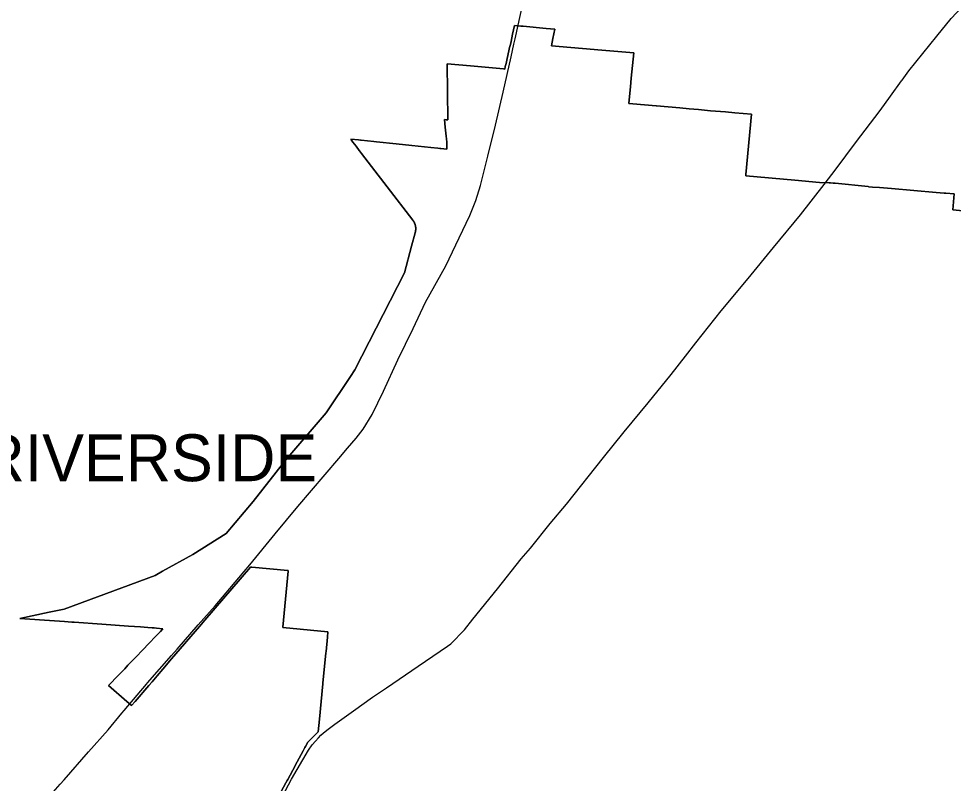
# Model space of a CAD drawing. Extents: x 0 to 34, y 0 to 22.
# Drawn here: x 5.4241 to 5.5845, y 15.3647 to 15.4958 of the extents above; entities that cross this region are included whole.
import ezdxf

# ---------------------------------------------------------------- set-up
doc = ezdxf.new("R2010")
doc.units = 0
for name, color, linetype in [('GM_X_Corporation', 7, 'Continuous'), ('GM_X_Corporation_Text', 7, 'Continuous'), ('GM_X_State_Route', 7, 'Continuous')]:
    doc.layers.add(name, color=color, linetype=linetype)

msp = doc.modelspace()

# ---------------------------------------------------------------- linework, layer by layer
at = {"layer": 'GM_X_Corporation'}
for points in [[(5.46726, 15.35978), (5.46998, 15.36478), (5.47019, 15.36518), (5.4703, 15.36537), (5.47154, 15.36769), (5.47159, 15.36777), (5.47291, 15.37024), (5.47293, 15.37027), (5.47306, 15.37051), (5.47311, 15.37061), (5.47317, 15.37071), (5.4732, 15.37078), (5.47322, 15.37081), (5.47333, 15.37102), (5.47371, 15.37172), (5.47554, 15.37351), (5.47575, 15.37568), (5.47633, 15.38176), (5.47634, 15.38184), (5.47684, 15.38706), (5.47687, 15.38731), (5.4771, 15.38975), (5.47719, 15.3907), (5.47718, 15.3907), (5.46942, 15.39144), (5.46942, 15.39149), (5.47034, 15.4011), (5.47035, 15.40118), (5.47031, 15.40118), (5.46413, 15.40177), (5.46389, 15.40179), (5.45607, 15.39269), (5.45514, 15.39161), (5.45034, 15.38602), (5.44886, 15.38429), (5.44787, 15.38313), (5.44702, 15.38212), (5.44646, 15.38148), (5.44408, 15.37871), (5.4435, 15.37802), (5.4431, 15.37836), (5.44303, 15.37842), (5.4427, 15.37871), (5.43952, 15.38145), (5.44008, 15.38203), (5.44017, 15.38212), (5.44064, 15.38261), (5.44098, 15.38297), (5.44175, 15.38377), (5.44231, 15.38435), (5.44287, 15.38494), (5.44343, 15.38552), (5.44398, 15.3861), (5.44454, 15.38668), (5.4451, 15.38726), (5.44566, 15.38784), (5.44622, 15.38842), (5.44663, 15.38886), (5.44677, 15.389), (5.44733, 15.38958), (5.44788, 15.39015), (5.44816, 15.39045), (5.44821, 15.3905), (5.44843, 15.39074), (5.44887, 15.39121), (5.44776, 15.3913), (5.44735, 15.39134), (5.44704, 15.39137), (5.4463, 15.39142), (5.44503, 15.39151), (5.44296, 15.39166), (5.43841, 15.39198), (5.43365, 15.39232), (5.43322, 15.39235), (5.43196, 15.39244), (5.43024, 15.39256), (5.4243, 15.39298), (5.42937, 15.39403), (5.4319, 15.39456), (5.44754, 15.40034), (5.4488, 15.40105), (5.454, 15.40396), (5.45975, 15.40755), (5.46434, 15.41304), (5.46996, 15.42018), (5.47687, 15.42823), (5.48108, 15.43448), (5.48182, 15.43559), (5.49033, 15.45223), (5.4915, 15.45682), (5.49216, 15.45913), (5.49218, 15.45918), (5.49218, 15.45918), (5.49218, 15.4592), (5.49218, 15.45921), (5.49219, 15.45922), (5.49219, 15.45922), (5.49219, 15.45924), (5.49219, 15.45925), (5.4922, 15.45926), (5.4922, 15.45926), (5.4922, 15.45928), (5.4922, 15.45929), (5.49221, 15.4593), (5.49221, 15.45931), (5.49221, 15.45932), (5.49221, 15.45933), (5.49221, 15.45934), (5.49222, 15.45935), (5.49222, 15.45936), (5.49222, 15.45937), (5.49222, 15.45938), (5.49222, 15.45939), (5.49223, 15.4594), (5.49223, 15.45941), (5.49223, 15.45942), (5.49223, 15.45943), (5.49223, 15.45944), (5.49223, 15.45946), (5.49224, 15.45946), (5.49224, 15.45947), (5.49224, 15.45948), (5.49224, 15.4595), (5.49224, 15.45951), (5.49224, 15.45951), (5.49224, 15.45953), (5.49224, 15.45954), (5.49225, 15.45955), (5.49225, 15.45956), (5.49225, 15.45957), (5.49225, 15.45958), (5.49225, 15.45959), (5.49225, 15.4596), (5.49225, 15.45961), (5.49225, 15.45962), (5.49225, 15.45963), (5.49225, 15.45964), (5.49225, 15.45965), (5.49226, 15.45967), (5.49226, 15.45967), (5.49226, 15.45968), (5.49226, 15.45969), (5.49226, 15.45971), (5.49226, 15.45972), (5.49226, 15.45972), (5.49226, 15.45974), (5.49226, 15.45975), (5.49226, 15.45976), (5.49226, 15.45977), (5.49226, 15.45978), (5.49226, 15.45979), (5.49226, 15.4598), (5.49226, 15.45981), (5.49226, 15.45982), (5.49226, 15.45983), (5.49226, 15.45984), (5.49226, 15.45985), (5.49226, 15.45986), (5.49226, 15.45988), (5.49226, 15.45988), (5.49226, 15.45989), (5.49226, 15.4599), (5.49226, 15.45992), (5.49226, 15.45993), (5.49226, 15.45993), (5.49226, 15.45995), (5.49225, 15.45996), (5.49225, 15.45997), (5.49225, 15.45998), (5.49225, 15.45999), (5.49225, 15.46), (5.49225, 15.46001), (5.49225, 15.46002), (5.49225, 15.46003), (5.49225, 15.46004), (5.49225, 15.46005), (5.49225, 15.46006), (5.49225, 15.46007), (5.49224, 15.46009), (5.49224, 15.46009), (5.49224, 15.4601), (5.49224, 15.46011), (5.49224, 15.46013), (5.49224, 15.46014), (5.49224, 15.46014), (5.49223, 15.46016), (5.49223, 15.46017), (5.49223, 15.46018), (5.49223, 15.46018), (5.49223, 15.4602), (5.49223, 15.46021), (5.49222, 15.46022), (5.49222, 15.46023), (5.49222, 15.46024), (5.49222, 15.46025), (5.49222, 15.46026), (5.49222, 15.46027), (5.49221, 15.46028), (5.49221, 15.46029), (5.49221, 15.4603), (5.49221, 15.46031), (5.4922, 15.46032), (5.4922, 15.46033), (5.4922, 15.46034), (5.4922, 15.46035), (5.4922, 15.46036), (5.49219, 15.46038), (5.49219, 15.46038), (5.49219, 15.46039), (5.49218, 15.4604), (5.49218, 15.46042), (5.49218, 15.46042), (5.49218, 15.46043), (5.49217, 15.46044), (5.49217, 15.46046), (5.49217, 15.46046), (5.49217, 15.46047), (5.49216, 15.46048), (5.49216, 15.4605), (5.49216, 15.4605), (5.49215, 15.46051), (5.49215, 15.46052), (5.49215, 15.46054), (5.49214, 15.46054), (5.49214, 15.46055), (5.49214, 15.46056), (5.49213, 15.46058), (5.49213, 15.46058), (5.49213, 15.46059), (5.49212, 15.4606), (5.49212, 15.46062), (5.49212, 15.46062), (5.49211, 15.46063), (5.49211, 15.46064), (5.49211, 15.46066), (5.4921, 15.46066), (5.4921, 15.46067), (5.49209, 15.46068), (5.49209, 15.4607), (5.49209, 15.4607), (5.49208, 15.46071), (5.49208, 15.46072), (5.49207, 15.46073), (5.49207, 15.46074), (5.49207, 15.46075), (5.49206, 15.46076), (5.49206, 15.46077), (5.49205, 15.46078), (5.49205, 15.46079), (5.49205, 15.4608), (5.49204, 15.46081), (5.49204, 15.46082), (5.49203, 15.46083), (5.49203, 15.46084), (5.49202, 15.46085), (5.49202, 15.46086), (5.49202, 15.46086), (5.49201, 15.46088), (5.492, 15.46089), (5.492, 15.46089), (5.492, 15.4609), (5.49199, 15.46091), (5.49199, 15.46091), (5.49198, 15.46093), (5.49198, 15.46093), (5.49198, 15.46094), (5.49197, 15.46095), (5.49197, 15.46096), (5.49196, 15.46097), (5.49196, 15.46098), (5.49195, 15.46099), (5.49194, 15.461), (5.49194, 15.46101), (5.49194, 15.46101), (5.49193, 15.46102), (5.49192, 15.46104), (5.49192, 15.46104), (5.49192, 15.46105), (5.49191, 15.46106), (5.49191, 15.46106), (5.4919, 15.46107), (5.4919, 15.46108), (5.49189, 15.46108), (5.49189, 15.4611), (5.49188, 15.46111), (5.49188, 15.46111), (5.49187, 15.46112), (5.49186, 15.46113), (5.49186, 15.46113), (5.49186, 15.46114), (5.49185, 15.46115), (5.49185, 15.46116), (5.49184, 15.46117), (5.49184, 15.46117), (5.49183, 15.46118), (5.49183, 15.46118), (5.49182, 15.46119), (5.49182, 15.4612), (5.49182, 15.4612), (5.49181, 15.46121), (5.4918, 15.46122), (5.4918, 15.46122), (5.49179, 15.46124), (5.49178, 15.46125), (5.49178, 15.46125), (5.49177, 15.46126), (5.49175, 15.46129), (5.48734, 15.46698), (5.48467, 15.47048), (5.48296, 15.47271), (5.4826, 15.47319), (5.48255, 15.47325), (5.48202, 15.47395), (5.48148, 15.47467), (5.4811, 15.47518), (5.48112, 15.47517), (5.48241, 15.47504), (5.48279, 15.475), (5.4829, 15.47499), (5.48509, 15.47476), (5.48553, 15.47472), (5.48889, 15.47437), (5.4916, 15.47409), (5.49485, 15.47376), (5.49606, 15.47363), (5.49639, 15.4736), (5.49655, 15.47358), (5.4976, 15.47348), (5.4976, 15.47469), (5.49738, 15.47674), (5.49733, 15.47726), (5.4972, 15.47852), (5.4975, 15.47849), (5.49778, 15.47847), (5.49778, 15.4785), (5.49762, 15.48811), (5.50163, 15.48775), (5.50733, 15.48722), (5.50752, 15.4872), (5.50763, 15.48765), (5.50775, 15.48818), (5.50787, 15.48872), (5.5083, 15.49059), (5.50843, 15.49114), (5.50844, 15.49117), (5.50861, 15.49191), (5.50888, 15.49316), (5.50921, 15.49467), (5.5097, 15.49462), (5.50974, 15.49462), (5.51028, 15.49457), (5.51071, 15.49453), (5.51466, 15.49417), (5.51615, 15.49403), (5.5158, 15.49246), (5.51553, 15.49121), (5.52421, 15.49045), (5.52967, 15.48998), (5.52925, 15.48566), (5.52911, 15.48414), (5.52884, 15.48135), (5.52883, 15.4813), (5.52949, 15.48124), (5.53152, 15.48106), (5.53152, 15.48106), (5.53353, 15.48089), (5.53355, 15.48088), (5.53756, 15.48053), (5.53757, 15.48053), (5.53916, 15.48039), (5.53917, 15.48039), (5.54076, 15.48025), (5.54078, 15.48025), (5.54284, 15.48006), (5.54286, 15.48006), (5.5454, 15.47984), (5.54543, 15.47984), (5.547, 15.4797), (5.54703, 15.47969), (5.54989, 15.47944), (5.54891, 15.46909), (5.54889, 15.46888), (5.55733, 15.46813), (5.56153, 15.46776), (5.5626, 15.46767), (5.56266, 15.46775), (5.56321, 15.4677), (5.56344, 15.46768), (5.56386, 15.46764), (5.56387, 15.46763), (5.56422, 15.4676), (5.56989, 15.46704), (5.57002, 15.46702), (5.57065, 15.46696), (5.57183, 15.46686), (5.57387, 15.46669), (5.58157, 15.46605), (5.58295, 15.46594), (5.58313, 15.46593), (5.58321, 15.46592), (5.58465, 15.46578), (5.58442, 15.46303), (5.59342, 15.46213)], [(5.59342, 15.46213), (5.58442, 15.46303), (5.58465, 15.46578), (5.58321, 15.46592), (5.58313, 15.46593), (5.58295, 15.46594), (5.58157, 15.46605), (5.57387, 15.46669), (5.57183, 15.46686), (5.57065, 15.46696), (5.57002, 15.46702), (5.56989, 15.46704), (5.56422, 15.4676), (5.56387, 15.46763), (5.56386, 15.46764), (5.56344, 15.46768), (5.56321, 15.4677), (5.56266, 15.46775), (5.5626, 15.46767), (5.56153, 15.46776), (5.55733, 15.46813), (5.54889, 15.46888), (5.54891, 15.46909), (5.54989, 15.47944), (5.54703, 15.47969), (5.547, 15.4797), (5.54543, 15.47984), (5.5454, 15.47984), (5.54286, 15.48006), (5.54284, 15.48006), (5.54078, 15.48025), (5.54076, 15.48025), (5.53917, 15.48039), (5.53916, 15.48039), (5.53757, 15.48053), (5.53756, 15.48053), (5.53355, 15.48088), (5.53353, 15.48089), (5.53152, 15.48106), (5.53152, 15.48106), (5.52949, 15.48124), (5.52883, 15.4813), (5.52884, 15.48135), (5.52911, 15.48414), (5.52925, 15.48566), (5.52967, 15.48998), (5.52421, 15.49045), (5.51553, 15.49121), (5.5158, 15.49246), (5.51615, 15.49403), (5.51466, 15.49417), (5.51071, 15.49453), (5.51028, 15.49457), (5.50974, 15.49462), (5.5097, 15.49462), (5.50921, 15.49467), (5.50888, 15.49316), (5.50861, 15.49191), (5.50844, 15.49117), (5.50843, 15.49114), (5.5083, 15.49059), (5.50787, 15.48872), (5.50775, 15.48818), (5.50763, 15.48765), (5.50752, 15.4872), (5.50733, 15.48722), (5.50163, 15.48775), (5.49762, 15.48811), (5.49778, 15.4785), (5.49778, 15.47847), (5.4975, 15.47849), (5.4972, 15.47852), (5.49733, 15.47726), (5.49738, 15.47674), (5.4976, 15.47468), (5.4976, 15.47348), (5.49655, 15.47358), (5.49639, 15.4736), (5.49606, 15.47363), (5.49485, 15.47376), (5.4916, 15.47409), (5.48889, 15.47437), (5.48553, 15.47472), (5.48509, 15.47476), (5.4829, 15.47499), (5.48279, 15.475), (5.48241, 15.47504), (5.48112, 15.47517), (5.4811, 15.47518), (5.48148, 15.47467), (5.48202, 15.47395), (5.48255, 15.47325), (5.4826, 15.47319), (5.48296, 15.47271), (5.48467, 15.47048), (5.48734, 15.46698), (5.49175, 15.46129), (5.49177, 15.46126), (5.49178, 15.46125), (5.49178, 15.46125), (5.49179, 15.46124), (5.4918, 15.46122), (5.4918, 15.46122), (5.49181, 15.46121), (5.49182, 15.4612), (5.49182, 15.4612), (5.49182, 15.46119), (5.49183, 15.46118), (5.49183, 15.46118), (5.49184, 15.46117), (5.49184, 15.46117), (5.49185, 15.46116), (5.49185, 15.46115), (5.49186, 15.46114), (5.49186, 15.46113), (5.49186, 15.46113), (5.49187, 15.46112), (5.49188, 15.46111), (5.49188, 15.46111), (5.49189, 15.4611), (5.49189, 15.46108), (5.4919, 15.46108), (5.4919, 15.46107), (5.49191, 15.46106), (5.49191, 15.46106), (5.49192, 15.46105), (5.49192, 15.46104), (5.49192, 15.46104), (5.49193, 15.46102), (5.49194, 15.46101), (5.49194, 15.46101), (5.49194, 15.461), (5.49195, 15.46099), (5.49196, 15.46098), (5.49196, 15.46097), (5.49197, 15.46096), (5.49197, 15.46095), (5.49198, 15.46094), (5.49198, 15.46093), (5.49198, 15.46093), (5.49199, 15.46091), (5.49199, 15.46091), (5.492, 15.4609), (5.492, 15.46089), (5.492, 15.46089), (5.49201, 15.46088), (5.49202, 15.46086), (5.49202, 15.46086), (5.49202, 15.46085), (5.49203, 15.46084), (5.49203, 15.46083), (5.49204, 15.46082), (5.49204, 15.46081), (5.49205, 15.4608), (5.49205, 15.46079), (5.49205, 15.46078), (5.49206, 15.46077), (5.49206, 15.46076), (5.49207, 15.46075), (5.49207, 15.46074), (5.49207, 15.46073), (5.49208, 15.46072), (5.49208, 15.46071), (5.49209, 15.4607), (5.49209, 15.4607), (5.49209, 15.46068), (5.4921, 15.46067), (5.4921, 15.46066), (5.49211, 15.46066), (5.49211, 15.46064), (5.49211, 15.46063), (5.49212, 15.46062), (5.49212, 15.46062), (5.49212, 15.4606), (5.49213, 15.46059), (5.49213, 15.46058), (5.49213, 15.46058), (5.49214, 15.46056), (5.49214, 15.46055), (5.49214, 15.46054), (5.49215, 15.46054), (5.49215, 15.46052), (5.49215, 15.46051), (5.49216, 15.4605), (5.49216, 15.4605), (5.49216, 15.46048), (5.49217, 15.46047), (5.49217, 15.46046), (5.49217, 15.46046), (5.49217, 15.46044), (5.49218, 15.46043), (5.49218, 15.46042), (5.49218, 15.46042), (5.49218, 15.4604), (5.49219, 15.46039), (5.49219, 15.46038), (5.49219, 15.46038), (5.4922, 15.46036), (5.4922, 15.46035), (5.4922, 15.46034), (5.4922, 15.46033), (5.4922, 15.46032), (5.49221, 15.46031), (5.49221, 15.4603), (5.49221, 15.46029), (5.49221, 15.46028), (5.49222, 15.46027), (5.49222, 15.46026), (5.49222, 15.46025), (5.49222, 15.46024), (5.49222, 15.46023), (5.49222, 15.46022), (5.49223, 15.46021), (5.49223, 15.4602), (5.49223, 15.46018), (5.49223, 15.46018), (5.49223, 15.46017), (5.49223, 15.46016), (5.49224, 15.46014), (5.49224, 15.46014), (5.49224, 15.46013), (5.49224, 15.46011), (5.49224, 15.4601), (5.49224, 15.46009), (5.49224, 15.46009), (5.49225, 15.46007), (5.49225, 15.46006), (5.49225, 15.46005), (5.49225, 15.46004), (5.49225, 15.46003), (5.49225, 15.46002), (5.49225, 15.46001), (5.49225, 15.46), (5.49225, 15.45999), (5.49225, 15.45998), (5.49225, 15.45997), (5.49225, 15.45996), (5.49226, 15.45995), (5.49226, 15.45993), (5.49226, 15.45993), (5.49226, 15.45992), (5.49226, 15.4599), (5.49226, 15.45989), (5.49226, 15.45988), (5.49226, 15.45988), (5.49226, 15.45986), (5.49226, 15.45985), (5.49226, 15.45984), (5.49226, 15.45983), (5.49226, 15.45982), (5.49226, 15.45981), (5.49226, 15.4598), (5.49226, 15.45979), (5.49226, 15.45978), (5.49226, 15.45977), (5.49226, 15.45976), (5.49226, 15.45975), (5.49226, 15.45974), (5.49226, 15.45972), (5.49226, 15.45972), (5.49226, 15.45971), (5.49226, 15.45969), (5.49226, 15.45968), (5.49226, 15.45967), (5.49226, 15.45967), (5.49225, 15.45965), (5.49225, 15.45964), (5.49225, 15.45963), (5.49225, 15.45962), (5.49225, 15.45961), (5.49225, 15.4596), (5.49225, 15.45959), (5.49225, 15.45958), (5.49225, 15.45957), (5.49225, 15.45956), (5.49225, 15.45955), (5.49224, 15.45954), (5.49224, 15.45953), (5.49224, 15.45951), (5.49224, 15.45951), (5.49224, 15.4595), (5.49224, 15.45948), (5.49224, 15.45947), (5.49224, 15.45946), (5.49223, 15.45946), (5.49223, 15.45944), (5.49223, 15.45943), (5.49223, 15.45942), (5.49223, 15.45941), (5.49223, 15.4594), (5.49222, 15.45939), (5.49222, 15.45938), (5.49222, 15.45937), (5.49222, 15.45936), (5.49222, 15.45935), (5.49221, 15.45934), (5.49221, 15.45933), (5.49221, 15.45932), (5.49221, 15.45931), (5.49221, 15.4593), (5.4922, 15.45929), (5.4922, 15.45928), (5.4922, 15.45926), (5.4922, 15.45926), (5.49219, 15.45925), (5.49219, 15.45924), (5.49219, 15.45922), (5.49219, 15.45922), (5.49218, 15.45921), (5.49218, 15.4592), (5.49218, 15.45918), (5.49218, 15.45918), (5.49216, 15.45913), (5.4915, 15.45682), (5.49033, 15.45223), (5.48182, 15.43559), (5.48108, 15.43448), (5.47687, 15.42823), (5.46996, 15.42018), (5.46434, 15.41304), (5.45975, 15.40755), (5.454, 15.40396), (5.4488, 15.40105), (5.44754, 15.40034), (5.4319, 15.39456), (5.42937, 15.39403), (5.4243, 15.39298), (5.43024, 15.39256), (5.43196, 15.39244), (5.43322, 15.39235), (5.43365, 15.39232), (5.43841, 15.39198), (5.44296, 15.39166), (5.44503, 15.39151), (5.4463, 15.39142), (5.44704, 15.39137), (5.44735, 15.39134), (5.44776, 15.3913), (5.44887, 15.39121), (5.44843, 15.39074), (5.44821, 15.3905), (5.44816, 15.39045), (5.44788, 15.39015), (5.44733, 15.38958), (5.44677, 15.389), (5.44663, 15.38886), (5.44622, 15.38842), (5.44566, 15.38784), (5.4451, 15.38726), (5.44454, 15.38668), (5.44398, 15.3861), (5.44343, 15.38552), (5.44287, 15.38494), (5.44231, 15.38435), (5.44175, 15.38377), (5.44098, 15.38297), (5.44064, 15.38261), (5.44017, 15.38212), (5.44008, 15.38203), (5.43952, 15.38145), (5.4427, 15.37871), (5.44303, 15.37842), (5.44309, 15.37837), (5.4431, 15.37836), (5.4435, 15.37802), (5.44408, 15.37871), (5.44646, 15.38148), (5.447, 15.38212), (5.44787, 15.38313), (5.44886, 15.38429), (5.45034, 15.38602), (5.45514, 15.39161), (5.45607, 15.39269), (5.46389, 15.40179), (5.46413, 15.40177), (5.47031, 15.40118), (5.47035, 15.40118), (5.47034, 15.4011), (5.46942, 15.39149), (5.46942, 15.39144), (5.47718, 15.3907), (5.47719, 15.3907), (5.4771, 15.38975), (5.47687, 15.38731), (5.47684, 15.38706), (5.47634, 15.38184), (5.47633, 15.38176), (5.47575, 15.37568), (5.47554, 15.37351), (5.47371, 15.37172), (5.47333, 15.37102), (5.47322, 15.37081), (5.47317, 15.37071), (5.47311, 15.37061), (5.47306, 15.37051), (5.47293, 15.37027), (5.47291, 15.37024), (5.47159, 15.36777), (5.47154, 15.36769), (5.4703, 15.36537), (5.47019, 15.36518), (5.46998, 15.36478), (5.46726, 15.35978)]]:
    msp.add_lwpolyline(points, dxfattribs=at)
at = {"layer": 'GM_X_State_Route'}
msp.add_line((5.56232, 15.46739), (5.56438, 15.47011), dxfattribs=at)
for points in [[(5.50911, 15.49145), (5.50931, 15.49238), (5.50981, 15.49475), (5.51133, 15.50156)], [(5.57561, 15.48518), (5.57571, 15.48531), (5.57688, 15.48691), (5.58167, 15.49283), (5.58416, 15.49587), (5.58683, 15.49875), (5.5882, 15.50027)], [(5.47908, 15.42041), (5.48054, 15.42215), (5.48203, 15.42389), (5.48322, 15.42544), (5.48476, 15.42794), (5.4867, 15.43198), (5.48921, 15.43735), (5.4918, 15.44271), (5.49392, 15.44722), (5.49743, 15.45347), (5.49973, 15.45827), (5.50153, 15.46211), (5.50256, 15.46463), (5.50339, 15.46721), (5.50461, 15.47228), (5.50592, 15.47755), (5.50728, 15.48321), (5.50862, 15.48927), (5.50911, 15.49145)], [(5.56438, 15.47011), (5.56772, 15.47454), (5.57195, 15.48012), (5.57371, 15.48255), (5.57561, 15.48518)], [(5.46885, 15.36151), (5.47093, 15.36543), (5.47383, 15.37035), (5.4745, 15.37128), (5.47503, 15.37194), (5.47556, 15.37252), (5.47598, 15.37293), (5.47645, 15.37334), (5.47722, 15.37399), (5.47836, 15.37482), (5.48157, 15.37715), (5.48485, 15.37945), (5.48725, 15.38108), (5.4927, 15.38477), (5.49771, 15.38821), (5.49828, 15.38864), (5.50061, 15.39104), (5.50206, 15.39286), (5.50627, 15.39804), (5.51036, 15.40317), (5.51194, 15.40502), (5.51534, 15.40923), (5.5181, 15.41259), (5.52448, 15.42056), (5.52802, 15.42498), (5.53214, 15.42997), (5.53609, 15.43482), (5.53857, 15.43796), (5.54033, 15.44026), (5.54465, 15.44573), (5.54931, 15.45125), (5.55366, 15.45661), (5.55828, 15.46219), (5.56232, 15.46739)], [(5.4628, 15.40103), (5.46378, 15.40219), (5.46815, 15.4075), (5.47204, 15.41219), (5.47674, 15.41764), (5.47908, 15.42041)], [(5.44623, 15.3819), (5.45034, 15.38659), (5.45129, 15.38771), (5.45494, 15.39185), (5.45781, 15.39511), (5.46035, 15.39813), (5.4628, 15.40103)], [(5.44184, 15.37675), (5.44221, 15.3772), (5.44607, 15.38171), (5.44623, 15.3819)], [(5.4206, 15.35163), (5.42126, 15.35239), (5.42765, 15.36041), (5.43126, 15.36455), (5.43193, 15.36531), (5.43612, 15.37007), (5.43946, 15.37385), (5.44184, 15.37675)]]:
    msp.add_lwpolyline(points, dxfattribs=at)

# ---------------------------------------------------------------- texts
at = {"layer": 'GM_X_Corporation_Text'}
msp.add_text('RIVERSIDE', height=0.008037, rotation=0, dxfattribs=at).set_placement((5.41741, 15.41651))

doc.saveas('drawing.dxf')
